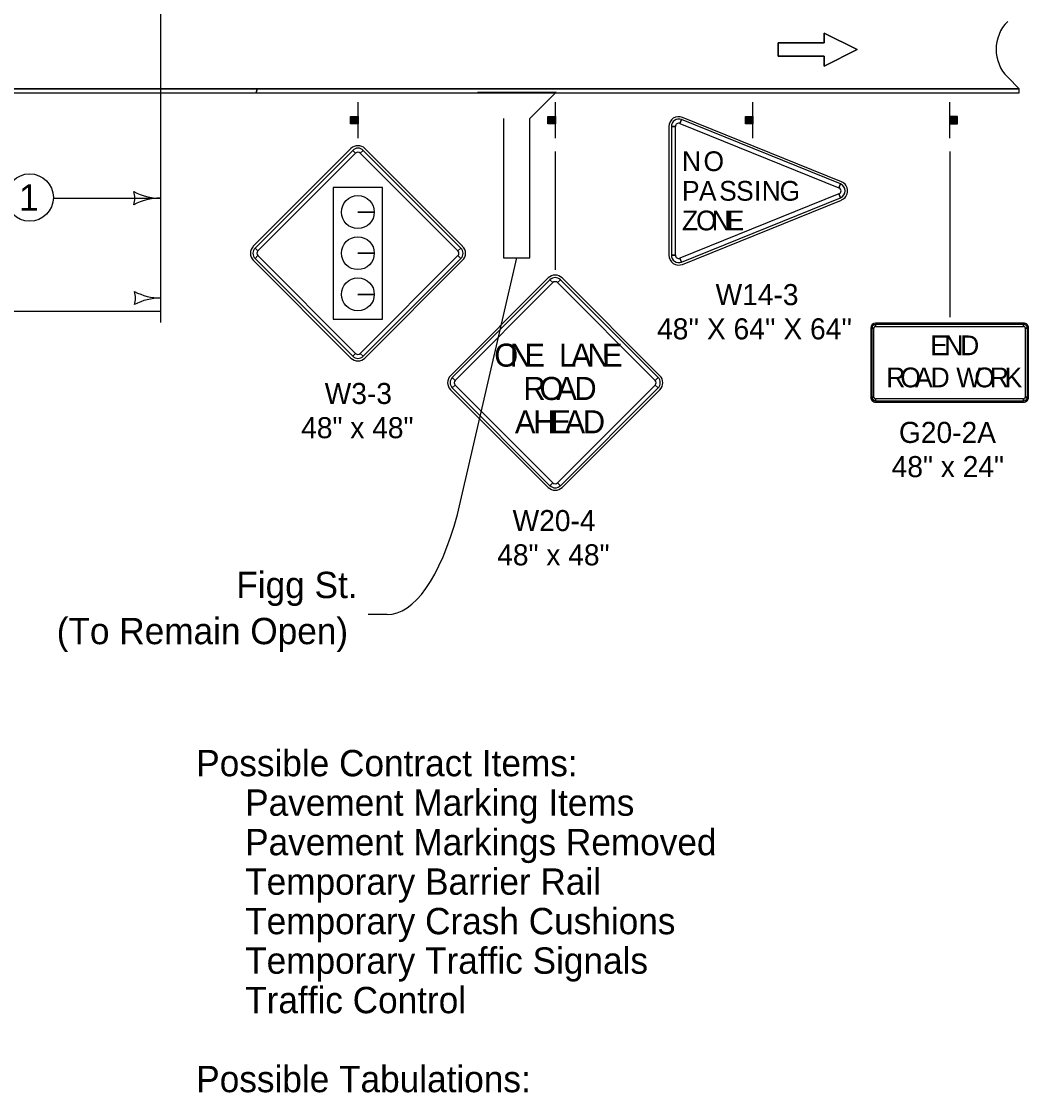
# Model space of a CAD drawing. Extents: x 10133 to 81668, y 4692 to 11018.
# Drawn here: x 23247 to 24012, y 6042 to 6856 of the extents above; entities that cross this region are included whole.
import ezdxf

# ---------------------------------------------------------------- set-up
doc = ezdxf.new("R2010")
doc.units = 0
for name, color, linetype in [('dsnCellElements', 7, 'Continuous'), ('dsnCellsNorthArrow', 7, 'Continuous'), ('dsnTextTabulation', 7, 'Continuous'), ('Level 8', 7, 'Continuous'), ('SheetAddendum', 7, 'Continuous'), ('SheetBorder', 7, 'Continuous')]:
    doc.layers.add(name, color=color, linetype=linetype)

msp = doc.modelspace()

# ---------------------------------------------------------------- linework, layer by layer
at = {"layer": 'dsnCellElements'}
for p, q in [((23352.53, 6627.2), (23352.53, 6864.8)), ((24004.98, 6804.8), (23996.2, 6813.59)), ((24004.98, 6804.8), (23996.2, 6813.59)), ((22502.53, 6804.8), (24004.98, 6804.8)), ((24004.98, 6801.8), (24004.98, 6804.8)), ((23502.53, 6767.3), (23502.53, 6794.8)), ((23652.53, 6767.3), (23652.53, 6794.8)), ((23802.53, 6767.3), (23802.53, 6794.8)), ((23952.34, 6767.3), (23952.34, 6794.8)), ((23497.2, 6778.17), (23497.2, 6783.75)), ((23497.52, 6783.75), (23497.52, 6778.17)), ((23497.75, 6778.17), (23497.75, 6783.75)), ((23498.06, 6783.75), (23498.06, 6778.17)), ((23498.29, 6778.17), (23498.27, 6783.75)), ((23498.7, 6783.75), (23498.72, 6778.17)), ((23498.93, 6778.17), (23498.93, 6783.75)), ((23499.36, 6783.75), (23499.36, 6778.17)), ((23499.73, 6778.17), (23499.73, 6783.75)), ((23500.05, 6783.75), (23500.07, 6778.17)), ((23500.28, 6778.17), (23500.28, 6783.75)), ((23500.54, 6783.75), (23500.54, 6778.17)), ((23500.88, 6778.17), (23500.88, 6783.75)), ((23501.08, 6783.75), (23501.08, 6778.17)), ((23501.31, 6778.17), (23501.31, 6783.75)), ((23501.57, 6783.75), (23501.57, 6778.17)), ((23501.83, 6778.17), (23501.83, 6783.75)), ((23502.11, 6783.75), (23502.11, 6778.17)), ((23647.2, 6778.17), (23647.2, 6783.75)), ((23647.52, 6783.75), (23647.52, 6778.17)), ((23647.75, 6778.17), (23647.75, 6783.75)), ((23648.06, 6783.75), (23648.06, 6778.17)), ((23648.29, 6778.17), (23648.27, 6783.75)), ((23648.7, 6783.75), (23648.72, 6778.17)), ((23648.93, 6778.17), (23648.93, 6783.75)), ((23649.36, 6783.75), (23649.36, 6778.17)), ((23649.73, 6778.17), (23649.73, 6783.75)), ((23650.05, 6783.75), (23650.07, 6778.17)), ((23650.28, 6778.17), (23650.28, 6783.75)), ((23650.54, 6783.75), (23650.54, 6778.17)), ((23650.88, 6778.17), (23650.88, 6783.75)), ((23651.08, 6783.75), (23651.08, 6778.17)), ((23651.31, 6778.17), (23651.31, 6783.75)), ((23651.57, 6783.75), (23651.57, 6778.17)), ((23651.83, 6778.17), (23651.83, 6783.75)), ((23652.11, 6783.75), (23652.11, 6778.17)), ((23797.2, 6778.17), (23797.2, 6783.75)), ((23797.52, 6783.75), (23797.52, 6778.17)), ((23797.75, 6778.17), (23797.75, 6783.75)), ((23798.06, 6783.75), (23798.06, 6778.17)), ((23798.29, 6778.17), (23798.27, 6783.75)), ((23798.7, 6783.75), (23798.72, 6778.17)), ((23798.93, 6778.17), (23798.93, 6783.75)), ((23799.36, 6783.75), (23799.36, 6778.17)), ((23799.73, 6778.17), (23799.73, 6783.75)), ((23800.05, 6783.75), (23800.07, 6778.17)), ((23800.28, 6778.17), (23800.28, 6783.75)), ((23800.54, 6783.75), (23800.54, 6778.17)), ((23800.88, 6778.17), (23800.88, 6783.75)), ((23801.08, 6783.75), (23801.08, 6778.17)), ((23801.31, 6778.17), (23801.31, 6783.75)), ((23801.57, 6783.75), (23801.57, 6778.17)), ((23801.83, 6778.17), (23801.83, 6783.75)), ((23802.11, 6783.75), (23802.11, 6778.17)), ((23952.75, 6783.75), (23952.75, 6778.17)), ((23953.03, 6778.17), (23953.03, 6783.75)), ((23953.29, 6783.75), (23953.29, 6778.17)), ((23953.56, 6778.17), (23953.56, 6783.75)), ((23953.78, 6783.75), (23953.78, 6778.17)), ((23953.99, 6778.17), (23953.99, 6783.75)), ((23954.33, 6783.75), (23954.33, 6778.17)), ((23954.59, 6778.17), (23954.59, 6783.75)), ((23954.81, 6783.75), (23954.79, 6778.17)), ((23955.13, 6778.17), (23955.13, 6783.75)), ((23955.51, 6783.75), (23955.51, 6778.17)), ((23955.94, 6778.17), (23955.94, 6783.75)), ((23956.16, 6783.75), (23956.14, 6778.17)), ((23956.58, 6778.17), (23956.59, 6783.75)), ((23956.8, 6783.75), (23956.8, 6778.17)), ((23957.12, 6778.17), (23957.12, 6783.75)), ((23957.34, 6783.75), (23957.34, 6778.17)), ((23957.66, 6778.17), (23957.66, 6783.75)), ((23652.53, 6667.3), (23652.53, 6757.3)), ((23952.53, 6631.25), (23952.53, 6757.3)), ((23270.89, 6721.73), (23352.04, 6721.73)), ((23578.12, 6481.47), (23623.09, 6676.35)), ((23137.53, 6635.87), (23352.53, 6635.87)), ((23524.5, 6405.41), (23510.28, 6405.41))]:
    msp.add_line(p, q, dxfattribs=at)
for points in [[(23821.71, 6839.63), (23821.71, 6829.63), (23856.71, 6829.63), (23856.71, 6822.13), (23881.71, 6834.63), (23856.71, 6847.13), (23856.71, 6839.63)], [(23502.43, 6783.75), (23502.43, 6778.13), (23496.81, 6778.13), (23496.81, 6783.75)], [(23652.43, 6783.75), (23652.43, 6778.13), (23646.81, 6778.13), (23646.81, 6783.75)], [(23802.43, 6783.75), (23802.43, 6778.13), (23796.81, 6778.13), (23796.81, 6783.75)], [(23952.43, 6783.75), (23952.43, 6778.13), (23958.06, 6778.13), (23958.06, 6783.75)]]:
    msp.add_lwpolyline(points, close=True, dxfattribs=at)
msp.add_lwpolyline([(23856.71, 6839.63), (23856.71, 6847.13), (23881.71, 6834.63), (23856.71, 6822.13), (23856.71, 6829.63), (23821.71, 6829.63), (23821.71, 6839.63), (23856.71, 6839.63)], dxfattribs=at)
msp.add_circle((23252.89, 6722.23), 18, dxfattribs=at)
for centre, radius, start, end in [((24017.41, 6834.8), 30, 135, 225), ((24017.41, 6834.8), 30, 135, 225), ((23316.4, 6721.73), 16.42, 342.26665, 17.73335), ((23352.04, 6764.23), 42.5, 241.92751, 270), ((23352.04, 6679.23), 42.5, 90, 118.07249)]:
    msp.add_arc(centre, radius, start, end, dxfattribs=at)
msp.add_ellipse((23524.5, 6618.34), major_axis=(0, -212.93), ratio=0.328743, start_param=0, end_param=0.872665, dxfattribs=at)
at = {"layer": 'dsnTextTabulation'}
for p, q in [((22502.53, 6804.8), (24004.98, 6804.8)), ((22502.53, 6804.8), (24004.98, 6804.8)), ((23425.92, 6804.8), (23152.04, 6804.8)), ((23424.91, 6801.8), (23425.92, 6804.8)), ((23425.92, 6804.8), (23424.91, 6801.8)), ((24004.98, 6804.8), (23425.92, 6804.8)), ((24004.98, 6801.8), (24004.98, 6804.8)), ((22502.53, 6801.8), (24004.98, 6801.8)), ((23152.04, 6801.8), (23424.91, 6801.8)), ((23424.91, 6801.8), (24004.98, 6801.8))]:
    msp.add_line(p, q, dxfattribs=at)
at = {"layer": 'Level 8'}
for centre, radius, start, end in [((23316.89, 6645.87), 16.42, 342.26665, 17.73335), ((23352.52, 6688.37), 42.5, 241.92751, 270), ((23352.52, 6603.37), 42.5, 90, 118.07249)]:
    msp.add_arc(centre, radius, start, end, dxfattribs=at)
at = {"layer": 'SheetAddendum'}
for p, q in [((23747.13, 6778.51), (23748.3, 6781.41)), ((23869.83, 6734.27), (23749, 6783.15)), ((23738.69, 6776.19), (23738.69, 6678.44)), ((23740.57, 6776.19), (23743.69, 6776.19)), ((23497.1, 6759.41), (23422.86, 6685.17)), ((23498.43, 6758.09), (23500.64, 6755.88)), ((23504.18, 6755.88), (23506.39, 6758.09)), ((23581.96, 6685.17), (23507.71, 6759.41)), ((23869.13, 6732.53), (23867.95, 6729.63)), ((23867.95, 6725), (23869.13, 6722.1)), ((23749, 6671.49), (23869.83, 6720.36)), ((23514.82, 6711.19), (23502.32, 6711.19)), ((23502.32, 6711.19), (23514.82, 6711.19)), ((23426.39, 6681.63), (23424.18, 6683.84)), ((23580.63, 6683.84), (23578.42, 6681.63)), ((23422.86, 6674.56), (23497.1, 6600.32)), ((23424.18, 6675.89), (23426.39, 6678.1)), ((23514.82, 6679.94), (23502.32, 6679.94)), ((23502.32, 6679.94), (23514.82, 6679.94)), ((23507.71, 6600.32), (23581.96, 6674.56)), ((23578.42, 6678.1), (23580.63, 6675.89)), ((23743.69, 6678.44), (23740.57, 6678.44)), ((23748.3, 6673.23), (23747.13, 6676.12)), ((23646.99, 6661.12), (23572.74, 6586.88)), ((23648.32, 6659.8), (23650.53, 6657.59)), ((23654.06, 6657.59), (23656.27, 6659.8)), ((23731.84, 6586.88), (23657.6, 6661.12)), ((23514.82, 6648.69), (23502.32, 6648.69)), ((23502.32, 6648.69), (23514.82, 6648.69)), ((24008.32, 6626.82), (23895.82, 6626.82)), ((23895.82, 6624.32), (23895.82, 6625.89)), ((24008.32, 6625.89), (24008.32, 6624.32)), ((23892.07, 6623.07), (23892.07, 6570.57)), ((23893, 6623.07), (23894.57, 6623.07)), ((24009.57, 6623.07), (24011.13, 6623.07)), ((24012.07, 6570.57), (24012.07, 6623.07)), ((23500.64, 6603.85), (23498.43, 6601.64)), ((23506.39, 6601.64), (23504.18, 6603.85)), ((23576.28, 6583.34), (23574.07, 6585.55)), ((23730.52, 6585.55), (23728.31, 6583.34)), ((23572.74, 6576.27), (23646.99, 6502.02)), ((23574.07, 6577.59), (23576.28, 6579.8)), ((23657.6, 6502.02), (23731.84, 6576.27)), ((23728.31, 6579.8), (23730.52, 6577.59)), ((23894.57, 6570.57), (23893, 6570.57)), ((23895.82, 6567.76), (23895.82, 6569.32)), ((23895.82, 6566.82), (24008.32, 6566.82)), ((24008.32, 6569.32), (24008.32, 6567.76)), ((24011.13, 6570.57), (24009.57, 6570.57)), ((23650.53, 6505.56), (23648.32, 6503.35)), ((23656.27, 6503.35), (23654.06, 6505.56))]:
    msp.add_line(p, q, dxfattribs=at)
for points in [[(23869.13, 6732.53), (23748.3, 6781.41), (23747.13, 6778.51), (23867.95, 6729.63), (23869.13, 6732.53)], [(23740.57, 6776.19), (23740.57, 6678.44), (23743.69, 6678.44), (23743.69, 6776.19), (23740.57, 6776.19)], [(23498.43, 6758.09), (23424.18, 6683.84), (23426.39, 6681.63), (23500.64, 6755.88), (23498.43, 6758.09)], [(23580.63, 6683.84), (23506.39, 6758.09), (23504.18, 6755.88), (23578.42, 6681.63), (23580.63, 6683.84)], [(23521.14, 6729.81), (23483.68, 6729.81), (23483.68, 6629.92), (23521.14, 6629.92), (23521.14, 6729.81)], [(23748.3, 6673.23), (23869.13, 6722.1), (23867.95, 6725), (23747.13, 6676.12), (23748.3, 6673.23)], [(23424.18, 6675.89), (23498.43, 6601.64), (23500.64, 6603.85), (23426.39, 6678.1), (23424.18, 6675.89)], [(23506.39, 6601.64), (23580.63, 6675.89), (23578.42, 6678.1), (23504.18, 6603.85), (23506.39, 6601.64)], [(23648.32, 6659.8), (23574.07, 6585.55), (23576.28, 6583.34), (23650.53, 6657.59), (23648.32, 6659.8)], [(23730.52, 6585.55), (23656.27, 6659.8), (23654.06, 6657.59), (23728.31, 6583.34), (23730.52, 6585.55)], [(24008.32, 6625.89), (23895.82, 6625.89), (23895.82, 6624.32), (24008.32, 6624.32), (24008.32, 6625.89)], [(23893, 6623.07), (23893, 6570.57), (23894.57, 6570.57), (23894.57, 6623.07), (23893, 6623.07)], [(24011.13, 6570.57), (24011.13, 6623.07), (24009.57, 6623.07), (24009.57, 6570.57), (24011.13, 6570.57)], [(23574.07, 6577.59), (23648.32, 6503.35), (23650.53, 6505.56), (23576.28, 6579.8), (23574.07, 6577.59)], [(23656.27, 6503.35), (23730.52, 6577.59), (23728.31, 6579.8), (23654.06, 6505.56), (23656.27, 6503.35)], [(23895.82, 6567.76), (24008.32, 6567.76), (24008.32, 6569.32), (23895.82, 6569.32), (23895.82, 6567.76)]]:
    msp.add_lwpolyline(points, close=True, dxfattribs=at)
for centre in [(23502.32, 6711.19), (23502.32, 6679.94), (23502.32, 6648.69)]:
    msp.add_circle(centre, 12.5, dxfattribs=at)
for centre, radius, start, end in [((23746.19, 6776.19), 7.5, 67.97571, 179.99985), ((23746.19, 6776.19), 5.62, 67.97571, 179.99985), ((23746.19, 6776.19), 2.5, 67.97571, 179.99985), ((23502.41, 6754.11), 7.5, 44.99999, 134.99974), ((23502.41, 6754.11), 5.62, 44.99999, 134.99974), ((23502.41, 6754.11), 2.5, 44.99999, 134.99974), ((23867.02, 6727.32), 2.5, 292.02456, 67.97541), ((23867.02, 6727.32), 5.62, 292.02456, 67.97541), ((23867.02, 6727.32), 7.5, 292.02456, 67.97598), ((23428.16, 6679.86), 7.5, 134.99974, 224.99995), ((23428.16, 6679.86), 5.62, 134.99974, 224.99995), ((23428.16, 6679.86), 2.5, 134.99974, 224.99995), ((23576.65, 6679.86), 2.5, 315.00016, 44.9998), ((23576.65, 6679.86), 5.62, 315.00016, 44.9998), ((23576.65, 6679.86), 7.5, 315.00016, 44.9998), ((23746.19, 6678.44), 7.5, 179.99985, 292.02456), ((23746.19, 6678.44), 5.62, 179.99985, 292.02456), ((23746.19, 6678.44), 2.5, 179.99985, 292.02456), ((23652.29, 6655.82), 7.5, 44.99999, 134.99974), ((23652.29, 6655.82), 5.62, 44.99999, 134.99974), ((23652.29, 6655.82), 2.5, 44.99999, 134.99974), ((23895.82, 6623.07), 3.75, 90.00021, 179.99985), ((23895.82, 6623.07), 2.81, 90.00021, 179.99985), ((23895.82, 6623.07), 1.25, 90.00021, 179.99985), ((24008.32, 6623.07), 3.75, 0, 90.00021), ((24008.32, 6623.07), 2.81, 0, 90.00021), ((24008.32, 6623.07), 1.25, 0, 90.00021), ((23502.41, 6605.62), 7.5, 224.99995, 315.00016), ((23502.41, 6605.62), 5.62, 224.99995, 315.00016), ((23502.41, 6605.62), 2.5, 224.99995, 315.00016), ((23578.05, 6581.57), 7.5, 134.99974, 224.99995), ((23578.05, 6581.57), 5.62, 134.99974, 224.99995), ((23578.05, 6581.57), 2.5, 134.99974, 224.99995), ((23726.54, 6581.57), 2.5, 315.00016, 44.9998), ((23726.54, 6581.57), 5.62, 315.00016, 44.9998), ((23726.54, 6581.57), 7.5, 315.00016, 44.9998), ((23895.82, 6570.57), 3.75, 179.99985, 270.00006), ((23895.82, 6570.57), 2.81, 179.99985, 270.00006), ((23895.82, 6570.57), 1.25, 179.99985, 270.00006), ((24008.32, 6570.57), 3.75, 270.00006, 0.00027), ((24008.32, 6570.57), 2.81, 270.00006, 0.00027), ((24008.32, 6570.57), 1.25, 270.00006, 0.00027), ((23652.29, 6507.33), 7.5, 224.99995, 315.00016), ((23652.29, 6507.33), 5.62, 224.99995, 315.00016), ((23652.29, 6507.33), 2.5, 224.99995, 315.00016)]:
    msp.add_arc(centre, radius, start, end, dxfattribs=at)
at = {"layer": 'SheetBorder'}
for p, q in [((23653.03, 6802.16), (23593.16, 6802.04)), ((23633.09, 6782.22), (23653.03, 6802.16)), ((23613.09, 6782.22), (23613.09, 6676.35)), ((23633.09, 6676.35), (23633.09, 6782.22)), ((23613.09, 6676.35), (23633.09, 6676.35))]:
    msp.add_line(p, q, dxfattribs=at)

# ---------------------------------------------------------------- texts
at = {"layer": 'dsnCellElements'}
msp.add_text('1', height=20, dxfattribs=at).set_placement((23244.83, 6712.23))
at = {"layer": 'dsnCellsNorthArrow'}
for s, p in [('Possible Contract Items:', (23379.51, 6282.6)), ('     Pavement Marking Items', (23379.51, 6252.6)), ('     Pavement Markings Removed', (23379.51, 6222.6)), ('     Temporary Barrier Rail', (23379.51, 6192.6)), ('     Temporary Crash Cushions', (23379.51, 6162.6)), ('     Temporary Traffic Signals', (23379.51, 6132.6)), ('     Traffic Control', (23379.51, 6102.6)), ('Possible Tabulations:', (23379.51, 6042.6))]:
    msp.add_text(s, height=20, dxfattribs=at).set_placement(p)
at = {"layer": 'SheetAddendum'}
for s, height, p in [('N', 15, (23748.66, 6742.32)), ('O', 15, (23765, 6742.32)), ('P', 15, (23748.66, 6719.82)), ('A', 15, (23761.55, 6719.82)), ('S', 15, (23776.9, 6719.82)), ('S', 15, (23789.79, 6719.82)), ('I', 15, (23803.39, 6719.82)), ('N', 15, (23809.25, 6719.82)), ('G', 15, (23822.84, 6719.82)), ('Z', 15, (23748.66, 6697.32)), ('O', 15, (23759.4, 6697.32)), ('N', 15, (23771.23, 6697.32)), ('E', 15, (23782.59, 6697.32)), ('W14-3', 16, (23774.2, 6640.49)), ("48'' X 64'' X 64''", 16, (23729.71, 6614.49)), ('E', 15, (23937.39, 6602.45)), ('N', 15, (23948.01, 6602.45)), ('D', 15, (23960.1, 6602.45)), ('O', 17.5, (23606.01, 6593.76)), ('N', 17.5, (23617.78, 6593.76)), ('E', 17.5, (23629.01, 6593.76)), ('L', 17.5, (23655.26, 6593.76)), ('A', 17.5, (23664.46, 6593.76)), ('N', 17.5, (23676.73, 6593.76)), ('E', 17.5, (23687.95, 6593.76)), ('R', 15, (23903.93, 6578.07)), ('O', 15, (23914.61, 6578.07)), ('A', 15, (23925.77, 6578.07)), ('D', 15, (23937.63, 6578.07)), ('W', 15, (23957.08, 6578.07)), ('O', 15, (23970.81, 6578.07)), ('R', 15, (23982.58, 6578.07)), ('K', 15, (23993.88, 6578.07)), ('R', 17.5, (23628.12, 6568.45)), ('O', 17.5, (23640.41, 6568.45)), ('A', 17.5, (23653.24, 6568.45)), ('D', 17.5, (23666.9, 6568.45)), ('W3-3', 16, (23477.12, 6565.4)), ('A', 17.5, (23621.68, 6543.13)), ('H', 17.5, (23635.54, 6543.13)), ('E', 17.5, (23648.76, 6543.13)), ('A', 17.5, (23659.47, 6543.13)), ('D', 17.5, (23673.34, 6543.13)), ('48" x 48"', 16, (23459.24, 6539.4)), ('G20-2A', 16, (23913.54, 6535.82)), ('48" x 24"', 16, (23908, 6509.82)), ('W20-4', 16, (23619.93, 6468.83)), ('48" x 48"', 16, (23608.23, 6442.83))]:
    msp.add_text(s, height=height, dxfattribs=at).set_placement(p)
at = {"layer": 'SheetBorder'}
for s, p in [('Figg St.', (23409.94, 6417.93)), ('(To Remain Open)', (23273.45, 6382.93))]:
    msp.add_text(s, height=20, dxfattribs=at).set_placement(p)

doc.saveas('drawing.dxf')
